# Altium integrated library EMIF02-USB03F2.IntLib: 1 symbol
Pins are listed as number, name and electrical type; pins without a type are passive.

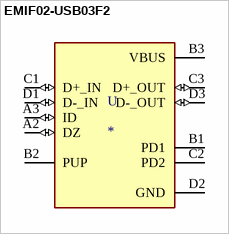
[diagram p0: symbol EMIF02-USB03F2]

## EMIF02-USB03F2
designator U
RC _Pi_ EMI Filter 2nd Order Low Pass 2 Channel R = 33Ohms, C = 20pF 11-WFBGA, FCBGA; MP: EMIF02-USB03F2; MF: STMicroelectronics
footprint BGA11N50P3X4_144X194X71N
pins: A2 DZ (io), A3 ID (io), B1 PD1, B2 PUP, B3 VBUS (power), C1 D+_IN (io), C2 PD2, C3 D+_OUT (io), D1 D-_IN (io), D2 GND (power), D3 D-_OUT (io)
